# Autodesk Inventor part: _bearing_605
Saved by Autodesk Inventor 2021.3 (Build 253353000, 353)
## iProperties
Created: 2021-10
Part Number: _bearing_605
Material: Generic
Document SubType Name: Modeling
Designer: Administrator
Density: 1 g/cm^3
Appearance: Default
Title: _bearing_605
Author: Administrator
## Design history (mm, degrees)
feature "Body1"
body "Solid1"
